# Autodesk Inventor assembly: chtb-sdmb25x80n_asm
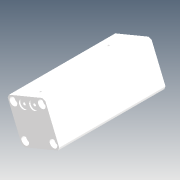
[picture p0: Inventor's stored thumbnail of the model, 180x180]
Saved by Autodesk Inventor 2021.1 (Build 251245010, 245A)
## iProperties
Company: Microsoft
Created: 2018-05
Part Number: chtb-sdmb25x80n_asm
Description: STEP AP214
Document SubType Name: Assembly
Designer: user
Title: chtb-sdmb25x80n_asm.STEP
Author: Windows
Revision Number: ÈÎºÎ
Sending System: SolidWorks 2015
Preprocessor: SwSTEP 2.0
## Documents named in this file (4)
- D:\Vault_2016\Projekty\Clamptek\Hydraulic\CHTB\CHTB-25\Inventor\chtb-sdmb25x80n\chtb-sdmb25x80n_asm.iam
- D:\Vault_2016\Projekty\Clamptek\Hydraulic\CHTB\CHTB-25\Inventor\chtb-sdmb25x80n\CHTB-25QG.ipt
- D:\Vault_2016\Projekty\Clamptek\Hydraulic\CHTB\CHTB-25\Inventor\chtb-sdmb25x80n\CHTB-SDMB25X80NBT.ipt
- D:\Vault_2016\Projekty\Clamptek\Hydraulic\CHTB\CHTB-25\Inventor\chtb-sdmb25x80n\CHTB-SDMB25X80NHSG.ipt
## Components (3 placed, 3 different names)
1. CHTB-25QG_1
2. CHTB-SDMB25X80NBT_2
3. CHTB-SDMB25X80NHSG_3
